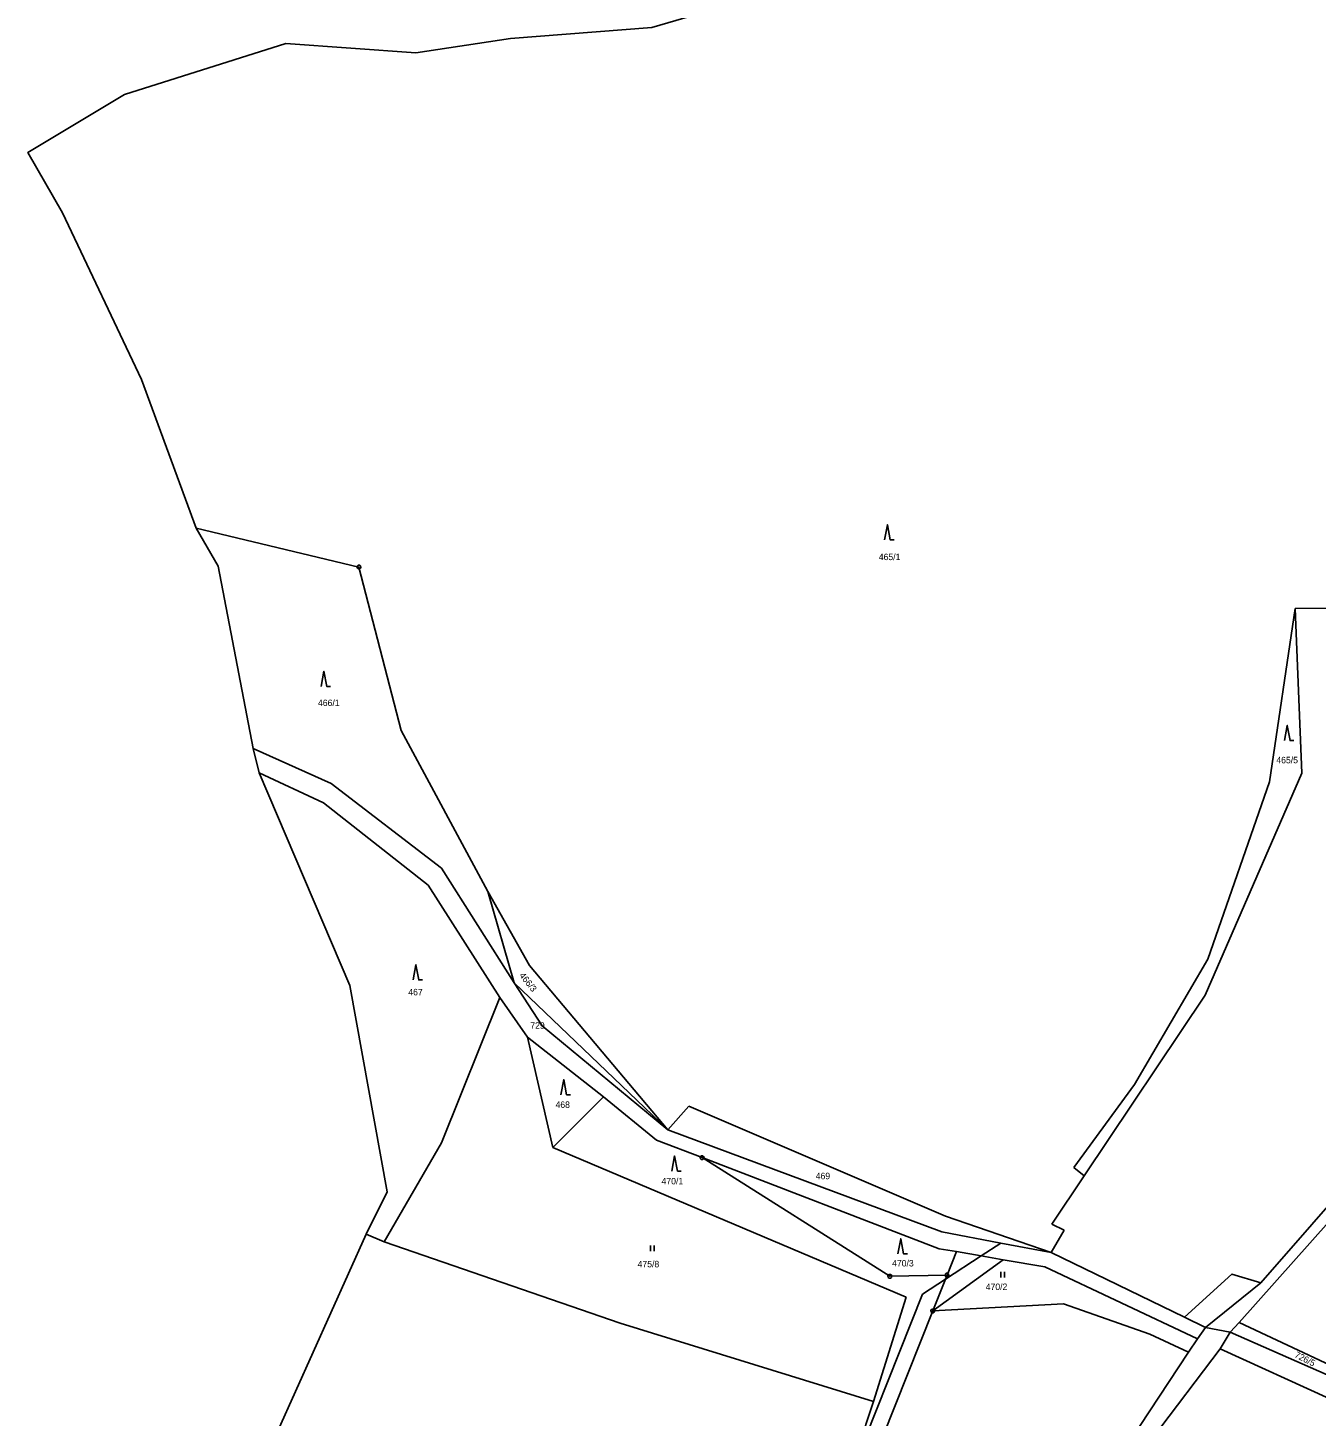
# Model space of a CAD drawing. Extents: x -694465 to -690527, y -983694 to -978978.
# Drawn here: x -694173.5 to -693834.3, y -981502.5 to -981137 of the extents above; entities that cross this region are included whole.
import ezdxf

# ---------------------------------------------------------------- set-up
doc = ezdxf.new("R2010")
doc.units = 0
for name, color, linetype in [('Vrstva 1', 7, 'Continuous'), ('Vrstva 18', 7, 'Continuous'), ('Vrstva 24', 7, 'Continuous'), ('Vrstva 25', 7, 'Continuous')]:
    doc.layers.add(name, color=color, linetype=linetype)

msp = doc.modelspace()

# ---------------------------------------------------------------- linework, layer by layer
at = {"layer": 'Vrstva 1'}
for points in [[(-694129.16, -981268.7), (-694143.47, -981229.56), (-694164.34, -981185.69), (-694173.45, -981169.83), (-694148.01, -981154.55), (-694105.53, -981141.09), (-694071.32, -981143.6), (-694046.38, -981139.79), (-694009.15, -981136.91), (-693980.91, -981128.58), (-693952.42, -981111.36), (-693913.39, -981085.93), (-693909.94, -981079.29)], [(-694086.28, -981278.92), (-694129.16, -981268.7)], [(-694114.14, -981326.7), (-694123.3, -981278.66), (-694129.16, -981268.7)], [(-694075.12, -981321.96), (-694086.28, -981278.92)], [(-693839.83, -981289.84), (-693846.63, -981335.43)], [(-693839.83, -981289.84), (-693799.27, -981289.63)], [(-693838.07, -981333.17), (-693839.83, -981289.84)], [(-694052.31, -981364.29), (-694075.12, -981321.96)], [(-694093.56, -981335.92), (-694114.14, -981326.7)], [(-694112.56, -981333.13), (-694114.14, -981326.7)], [(-694084.41, -981454.56), (-694078.86, -981443.4), (-694088.64, -981389.07), (-694112.56, -981333.13)], [(-694112.56, -981333.13), (-694095.63, -981340.96)], [(-693863.54, -981391.61), (-693838.07, -981333.17)], [(-694064.53, -981358.22), (-694093.56, -981335.92)], [(-693846.63, -981335.43), (-693862.84, -981382.11)], [(-694095.63, -981340.96), (-694068.06, -981362.67)], [(-694045.4, -981388.39), (-694064.53, -981358.22)], [(-694068.06, -981362.67), (-694049.19, -981392.28)], [(-694041.39, -981383.85), (-694052.31, -981364.29)], [(-694052.31, -981364.29), (-694045.4, -981388.39)], [(-694005, -981427.11), (-694041.39, -981383.85)], [(-693862.84, -981382.11), (-693882.09, -981415.17)], [(-694005, -981427.11), (-694045.4, -981388.39)], [(-694045.4, -981388.39), (-694038.02, -981399.685), (-694005, -981427.11)], [(-693895.34, -981439.15), (-693863.54, -981391.61)], [(-694064.56, -981430.51), (-694049.19, -981392.28)], [(-694049.19, -981392.28), (-694041.87, -981402.68)], [(-694041.87, -981402.68), (-694035.2, -981431.74)], [(-694041.87, -981402.68), (-694021.88, -981418.4)], [(-693882.09, -981415.17), (-693898.13, -981437)], [(-694021.88, -981418.4), (-694035.2, -981431.74)], [(-694021.88, -981418.4), (-694007.95, -981429.77)], [(-693999.44, -981420.83), (-694005, -981427.11)], [(-693931.89, -981449.82), (-693999.44, -981420.83)], [(-693854.56, -981477.77), (-693806.67, -981423.98)], [(-693809.17, -981422.01), (-693848.91, -981467.31)], [(-693932.88, -981453.94), (-694005, -981427.11)], [(-694079.62, -981456.56), (-694064.56, -981430.51)], [(-694035.2, -981431.74), (-693942.23, -981471.15)], [(-694007.95, -981429.77), (-693995.94, -981434.39)], [(-693995.94, -981434.39), (-693946.53, -981465.61)], [(-693995.94, -981434.39), (-693933.53, -981458.36)], [(-693903.87, -981451.9), (-693895.34, -981439.15)], [(-693898.13, -981437), (-693895.34, -981439.15)], [(-693904.1, -981459.36), (-693931.89, -981449.82)], [(-693917.304, -981456.873), (-693932.88, -981453.94)], [(-693904.1, -981459.36), (-693900.61, -981453.47)], [(-693900.61, -981453.47), (-693903.87, -981451.9)], [(-694107.65, -981506.35), (-694084.41, -981454.56)], [(-694084.41, -981454.56), (-694079.62, -981456.56)], [(-694079.62, -981456.56), (-694017.53, -981477.97)], [(-693922.492, -981460.267), (-693917.304, -981456.873)], [(-693904.1, -981459.36), (-693917.304, -981456.873)], [(-693935.22, -981474.75), (-693916.726, -981461.266)], [(-693933.53, -981458.36), (-693929, -981459.14)], [(-693931.909, -981466.427), (-693922.492, -981460.267)], [(-693931.46, -981465.3), (-693929, -981459.14)], [(-693929, -981459.14), (-693922.492, -981460.267)], [(-693922.492, -981460.267), (-693916.726, -981461.266)], [(-693916.726, -981461.266), (-693905.73, -981463.17)], [(-693868.974, -981476.379), (-693904.1, -981459.36)], [(-693905.73, -981463.17), (-693865.55, -981482.05)], [(-693959.11, -981523.52), (-693937.9, -981470.347), (-693931.909, -981466.427)], [(-693946.53, -981465.61), (-693931.46, -981465.3)], [(-693935.22, -981474.75), (-693931.909, -981466.427)], [(-693931.909, -981466.427), (-693931.46, -981465.3)], [(-693868.974, -981476.379), (-693856.495, -981465.029), (-693848.91, -981467.31)], [(-693848.91, -981467.31), (-693863.42, -981479.07)], [(-693942.23, -981471.15), (-693950.83, -981498.58)], [(-693955.07, -981524.58), (-693935.22, -981474.75)], [(-693935.22, -981474.75), (-693900.85, -981472.85)], [(-693900.85, -981472.85), (-693878.12, -981480.84)], [(-694017.53, -981477.97), (-693950.83, -981498.58)], [(-693863.42, -981479.07), (-693868.974, -981476.379)], [(-693863.42, -981479.07), (-693865.55, -981482.05)], [(-693856.93, -981480.36), (-693863.42, -981479.07)], [(-693854.56, -981477.77), (-693856.93, -981480.36)], [(-693819.18, -981494.41), (-693854.56, -981477.77)], [(-693878.12, -981480.84), (-693867.89, -981485.59)], [(-693865.55, -981482.05), (-693867.89, -981485.59)], [(-693856.93, -981480.36), (-693859.6, -981484.7)], [(-693820.43, -981496.42), (-693856.93, -981480.36)], [(-693867.89, -981485.59), (-693885.93, -981512.91)], [(-693877.43, -981508.24), (-693859.6, -981484.7)], [(-693859.6, -981484.7), (-693830.69, -981497.86)], [(-693950.83, -981498.58), (-693959.11, -981523.52)]]:
    msp.add_lwpolyline(points, dxfattribs=at)
at = {"layer": 'Vrstva 24'}
for points in [[(-694086.126, -981278.444), (-694085.876, -981278.626), (-694085.78, -981278.92), (-694085.876, -981279.214), (-694086.126, -981279.396), (-694086.434, -981279.396), (-694086.684, -981279.214), (-694086.78, -981278.92), (-694086.684, -981278.626), (-694086.434, -981278.444)], [(-693995.786, -981433.914), (-693995.536, -981434.096), (-693995.44, -981434.39), (-693995.536, -981434.684), (-693995.786, -981434.866), (-693996.094, -981434.866), (-693996.344, -981434.684), (-693996.44, -981434.39), (-693996.344, -981434.096), (-693996.094, -981433.914)], [(-693931.306, -981464.824), (-693931.056, -981465.006), (-693930.96, -981465.3), (-693931.056, -981465.594), (-693931.306, -981465.776), (-693931.614, -981465.776), (-693931.864, -981465.594), (-693931.96, -981465.3), (-693931.864, -981465.006), (-693931.614, -981464.824)], [(-693946.376, -981465.134), (-693946.126, -981465.316), (-693946.03, -981465.61), (-693946.126, -981465.904), (-693946.376, -981466.086), (-693946.684, -981466.086), (-693946.934, -981465.904), (-693947.03, -981465.61), (-693946.934, -981465.316), (-693946.684, -981465.134)], [(-693935.066, -981474.274), (-693934.816, -981474.456), (-693934.72, -981474.75), (-693934.816, -981475.044), (-693935.066, -981475.226), (-693935.374, -981475.226), (-693935.624, -981475.044), (-693935.72, -981474.75), (-693935.624, -981474.456), (-693935.374, -981474.274)]]:
    msp.add_lwpolyline(points, close=True, dxfattribs=at)
for points in [[(-694086.399, -981278.92), (-694086.16, -981278.92)], [(-693996.059, -981434.39), (-693995.82, -981434.39)], [(-693946.649, -981465.61), (-693946.41, -981465.61)], [(-693931.579, -981465.3), (-693931.34, -981465.3)], [(-693935.339, -981474.75), (-693935.1, -981474.75)]]:
    msp.add_lwpolyline(points, dxfattribs=at)
at = {"layer": 'Vrstva 25'}
for points in [[(-693947.92, -981271.8), (-693947.17, -981267.8), (-693946.42, -981271.8), (-693945.42, -981271.8)], [(-694096.25, -981310.34), (-694095.5, -981306.34), (-694094.75, -981310.34), (-694093.75, -981310.34)], [(-693842.66, -981324.59), (-693841.91, -981320.59), (-693841.16, -981324.59), (-693840.16, -981324.59)], [(-694072.02, -981387.6), (-694071.27, -981383.6), (-694070.52, -981387.6), (-694069.52, -981387.6)], [(-694033.11, -981417.83), (-694032.36, -981413.83), (-694031.61, -981417.83), (-694030.61, -981417.83)], [(-694003.92, -981437.95), (-694003.17, -981433.95), (-694002.42, -981437.95), (-694001.42, -981437.95)], [(-694009.57, -981457.51), (-694009.57, -981459.01)], [(-694008.57, -981459.01), (-694008.57, -981457.51)], [(-693944.41, -981459.75), (-693943.66, -981455.75), (-693942.91, -981459.75), (-693941.91, -981459.75)], [(-693917.32, -981464.45), (-693917.32, -981465.95)], [(-693916.32, -981465.95), (-693916.32, -981464.45)]]:
    msp.add_lwpolyline(points, dxfattribs=at)

# ---------------------------------------------------------------- texts
at = {"layer": 'Vrstva 18'}
for s, p in [('465/1', (-693949.433, -981277.1)), ('466/1', (-694097.053, -981315.52)), ('465/5', (-693844.783, -981330.58)), ('467', (-694073.284, -981391.66)), ('729', (-694041.168, -981400.46)), ('468', (-694034.534, -981421.31)), ('469', (-693966.044, -981440.07)), ('470/1', (-694006.622, -981441.43)), ('470/3', (-693945.933, -981463.04)), ('475/8', (-694012.92, -981463.26)), ('470/2', (-693921.283, -981469.24))]:
    msp.add_text(s, height=1.7, dxfattribs=at).set_placement(p)
for s, rotation, p in [('466/3', 308.70966, (-694044.181, -981386.493)), ('726/5', 333.00307, (-693840.161, -981486.855))]:
    msp.add_text(s, height=1.7, rotation=rotation, dxfattribs=at).set_placement(p)

doc.saveas('drawing.dxf')
